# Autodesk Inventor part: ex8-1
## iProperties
Author: Administrator
Created: 2001-03
Part Number: ex8-1
Document SubType Name: Modeling
Designer: Administrator
Control State: 0
Master: False
Checked Out: False
PropertySet Name: Design Tracking Control
Shininess: 20.0
PropertySet Name: _Private Model Information
Density: 0.0
Volumn: 0.0
Area: 0.0
PropertySet Name: Model Information
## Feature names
1. Extrusion1
2. Extrusion2
